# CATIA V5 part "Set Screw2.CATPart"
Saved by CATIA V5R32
Part number: Set Screw-16
Bounding box of the stored display mesh (mm): x -5.367 to 5.367, y -5.448 to 5.448, z -1.732 to 20
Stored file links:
  D:\PROJECTS\Project 2022\CATIA V5 6R 2022\Resources\Tutorial Files\c13_catia_v5_6r2022_tut\c13tut2\Bench vice\Set Screw2.CATPart
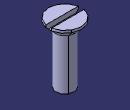
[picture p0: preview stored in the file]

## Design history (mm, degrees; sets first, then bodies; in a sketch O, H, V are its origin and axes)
Body1 (main body)
  Sketch1 on yz-plane, origin (0, 0, 0), H (0, 1, 0), V (0, 0, 1)
    point P1 (0, -1.7321)
    line L1 (0, -1.7321) -> (3, 0)
    point P2 (3, 0)
    line L2 (3, 0) -> (3, 16.7)
    point P3 (3, 16.7)
    line L3 (3, 16.7) -> (5.45, 19.15)
    point P4 (6, 20.1711)
    line L4 (5.45, 20) -> (0, 20)
    point P5 (0, 20)
    line L5 (0, 20) -> (0, -1.7321)
    line L6 (5.45, 20) -> (5.45, 19.15)
    distance L2 L5 = 3
    angle L1 L5 = 60
    distance L4 P2 = 20
    distance L6 L5 = 5.45
    distance L4 P3 = 3.3
    angle L3 L5 = 45
    coincidence: P1 V, P2 H, P5 V
    vertical: L2 V, L5 V, L6 V
    horizontal: L4 H
  Shaft1: profile Sketch1, axis edge of Sketch1, angle 360
  Sketch2 on yz-plane, origin (0, 0, 0), H (0, 1, 0), V (0, 0, 1)
    line L1 (-0.95, 25.2747) -> (0.95, 25.2747)
    line L2 (0.95, 25.2747) -> (0.95, 18.4)
    line L3 (0.95, 18.4) -> (-0.95, 18.4)
    line L4 (-0.95, 18.4) -> (-0.95, 25.2747)
    reference projected line E1 (5.45, 20) -> (-5.45, 20) from edge [face of Shaft1 from Sketch1.L4 | face of Shaft1 from Sketch1.L6]
    distance L4 L2 = 1.9
    distance L3 E1 = 1.6
    horizontal: L1 H, L3 H
    vertical: L2 V, L4 V
    symmetry: L2 L4 V
  Pocket1: profile Sketch2, direction (-1, 0, 0), length 16, mirrored extent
